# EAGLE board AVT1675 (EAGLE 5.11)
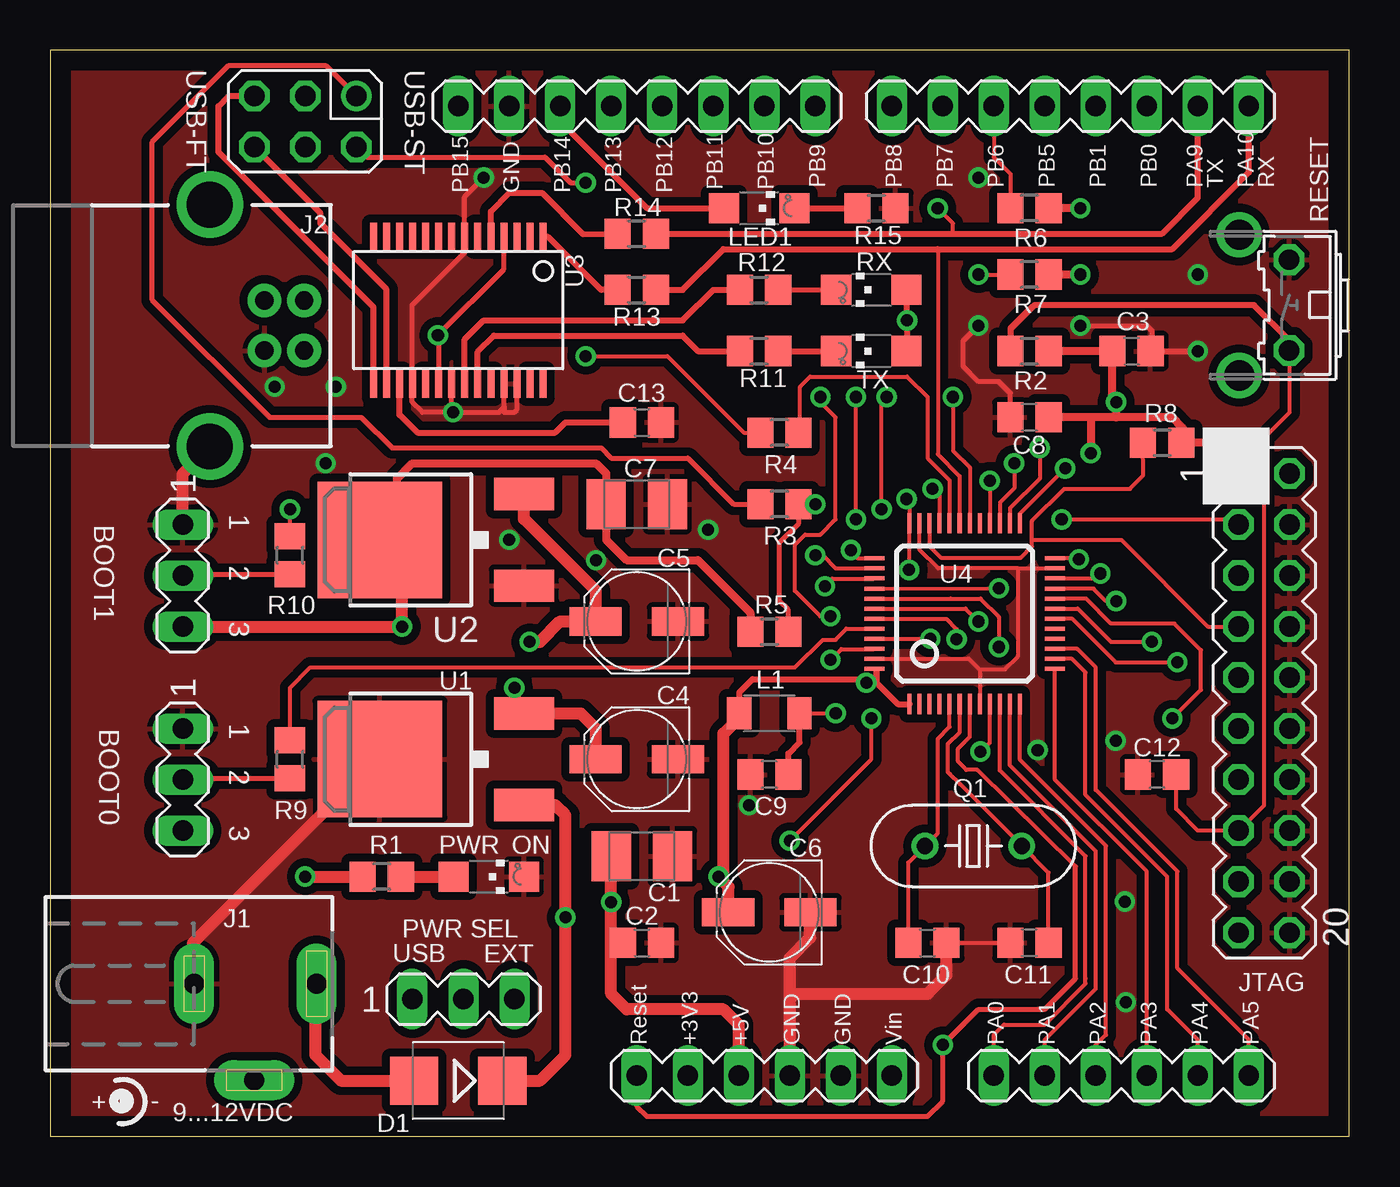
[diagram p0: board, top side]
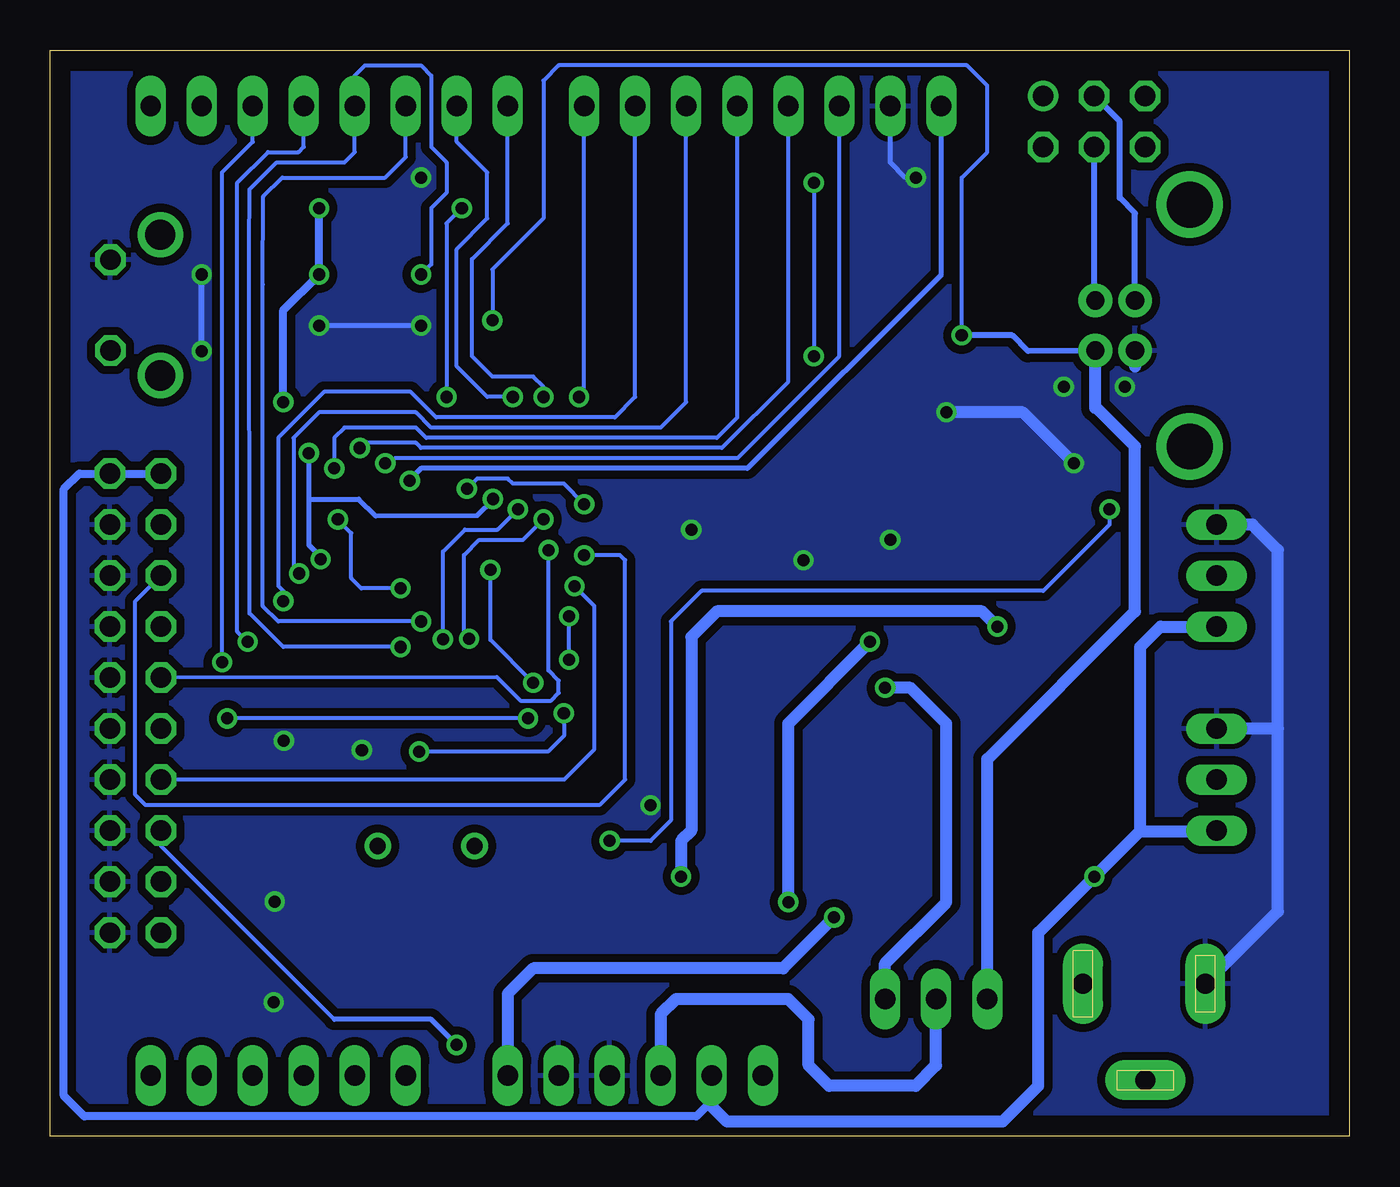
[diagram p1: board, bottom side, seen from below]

Size 64.69 x 54.07 mm. Coordinates in mm from the lower left corner, seen from the top.
Outline: 0,0 64.69,0 64.69,54.07 0,54.07 0,0
Copper layers (1*16): Top 0.035mm / dielectric 1.5mm / Bottom 0.035mm
Design rules "default *": minimum track width 8mil, minimum drill 24mil, track to track 8mil, track to pad 8mil, pad to pad 8mil, via to via 8mil, smd to smd 8mil, copper to edge 40mil, drill to drill 8mil, minimum pad ring 10mil, minimum via ring 8mil, stop-mask expansion 4mil, vias tented up to drill 0mil, thermal gap 10mil

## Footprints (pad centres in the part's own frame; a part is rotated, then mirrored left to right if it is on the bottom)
MA03-1 = drill 1.016 long: 1 -2.54,0; 2 0,0; 3 2.54,0
B/3528-21R = smd 1.95 x 2.5: + 1.525,0; - -1.525,0
C0805 = smd 1.3 x 1.5: 1 -0.95,0; 2 0.95,0
PANASONIC_C = smd 2.6 x 1.4: + 2.05,0; - -2.05,0
SMB = smd 2.4 x 2.4: A 2.2,0; C -2.2,0
DCJ0202 = drill 1 pad 2 long: 1 0,3.1; 2 4.8,0; 3 0,-3
USB-B-PTH = drill 0.914 pad 1.676 round: D+ 0,1.25; D- 1.981,1.25; GND 0,-1.25; VBUS 1.981,-1.25 | drill 2.286 round: P$1 -2.718,-6.02; P$2 -2.718,6.02
MA10-2 = drill 1.016 octagon: 1 -11.43,-1.27; 2 -11.43,1.27; 3 -8.89,-1.27; 4 -8.89,1.27; 5 -6.35,-1.27; 6 -6.35,1.27; 7 -3.81,-1.27; 8 -3.81,1.27; 9 -1.27,-1.27; 10 -1.27,1.27; 11 1.27,-1.27; 12 1.27,1.27; 13 3.81,-1.27; 14 3.81,1.27; 15 6.35,-1.27; 16 6.35,1.27; 17 8.89,-1.27; 18 8.89,1.27; 19 11.43,-1.27; 20 11.43,1.27
L3216C = smd 1.2 x 1.6: 1 -1.5,0; 2 1.5,0
CHIPLED_1206 = smd 1.5 x 1.5: A 0,-1.75; C 0,1.75
HC49U70 = drill 0.813 round: 1 -2.413,0; 2 2.413,0
R0805 = smd 1.3 x 1.5: 1 -0.95,0; 2 0.95,0
B3F-31XX = drill 1.016 octagon: 1 -2.261,-1.245; 2 2.261,-1.245 | drill 1.499 pad 2.159 round: 3 -3.505,1.245; 4 3.505,1.245
MA06-1 = drill 1.016 long: 1 -6.35,0; 2 -3.81,0; 3 -1.27,0; 4 1.27,0; 5 3.81,0; 6 6.35,0
MA08-1 = drill 1.016 long: 1 -8.89,0; 2 -6.35,0; 3 -3.81,0; 4 -1.27,0; 5 1.27,0; 6 3.81,0; 7 6.35,0; 8 8.89,0
DPACK = smd 1.6 x 3: 1 -2.28,-4.8; 3 2.28,-4.8 | smd 5.8 x 6.2: 4 0,2.38
SSOP28DB = smd 0.348 x 1.397: 1 -4.225,-3.656; 2 -3.575,-3.656; 3 -2.925,-3.656; 4 -2.275,-3.656; 5 -1.625,-3.656; 6 -0.975,-3.656; 7 -0.325,-3.656; 8 0.325,-3.656; 9 0.975,-3.656; 10 1.625,-3.656; 11 2.275,-3.656; 12 2.925,-3.656; 13 3.575,-3.656; 14 4.225,-3.656; 15 4.225,3.656; 16 3.575,3.656; 17 2.925,3.656; 18 2.275,3.656; 19 1.625,3.656; 20 0.975,3.656; 21 0.325,3.656; 22 -0.325,3.656; 23 -0.975,3.656; 24 -1.625,3.656; 25 -2.275,3.656; 26 -2.925,3.656; 27 -3.575,3.656; 28 -4.225,3.656
TQFP48 = smd 0.2 x 1: 1 -2.75,-4.5; 2 -2.25,-4.5; 3 -1.75,-4.5; 4 -1.25,-4.5; 5 -0.75,-4.5; 6 -0.25,-4.5; 7 0.25,-4.5; 8 0.75,-4.5; 9 1.25,-4.5; 10 1.75,-4.5; 11 2.25,-4.5; 12 2.75,-4.5; 25 2.75,4.5; 26 2.25,4.5; 27 1.75,4.5; 28 1.25,4.5; 29 0.75,4.5; 30 0.25,4.5; 31 -0.25,4.5; 32 -0.75,4.5; 33 -1.25,4.5; 34 -1.75,4.5; 35 -2.25,4.5; 36 -2.75,4.5 | smd 1 x 0.2: 13 4.5,-2.75; 14 4.5,-2.25; 15 4.5,-1.75; 16 4.5,-1.25; 17 4.5,-0.75; 18 4.5,-0.25; 19 4.5,0.25; 20 4.5,0.75; 21 4.5,1.25; 22 4.5,1.75; 23 4.5,2.25; 24 4.5,2.75; 37 -4.5,2.75; 38 -4.5,2.25; 39 -4.5,1.75; 40 -4.5,1.25; 41 -4.5,0.75; 42 -4.5,0.25; 43 -4.5,-0.25; 44 -4.5,-0.75; 45 -4.5,-1.25; 46 -4.5,-1.75; 47 -4.5,-2.25; 48 -4.5,-2.75
MA03-2 = drill 1.016 round: 1 -2.54,-1.27 | drill 1.016 octagon: 2 -2.54,1.27; 3 0,-1.27; 4 0,1.27; 5 2.54,-1.27; 6 2.54,1.27

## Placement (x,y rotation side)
BOOT0  [MA03-1]  6.6,17.75 270 top
BOOT1  [MA03-1]  6.6,27.91 270 top
C1  10uF  [B/3528-21R]  29.46,13.94 180 top
C2  100nF  [C0805]  29.46,9.63 0 top
C3  100nF  [C0805]  53.85,39.09 0 top
C4  [PANASONIC_C]  29.21,18.77 180 top
C5  [PANASONIC_C]  29.21,25.63 180 top
C6  [PANASONIC_C]  35.81,11.15 180 top
C7  10uF  [B/3528-21R]  29.21,31.47 180 top
C8  100nF  [C0805]  48.77,35.79 180 top
C9  100nF  [C0805]  35.81,18.01 180 top
C10  22pF  [C0805]  43.69,9.63 0 top
C11  22pF  [C0805]  48.77,9.63 180 top
C12  100nF  [C0805]  55.12,18.01 180 top
C13  100nF  [C0805]  29.46,35.53 0 top
D1  [SMB]  20.32,2.77 180 top
J1  [DCJ0202]  10.16,7.59 270 top
J2  USBPTH  [USB-B-PTH]  10.67,40.36 0 top
JTAG  [MA10-2]  60.45,21.56 270 top
L1  [L3216C]  35.81,21.06 180 top
LED1  [CHIPLED_1206]  35.31,46.2 270 top
PWR  [CHIPLED_1206]  21.84,12.93 270 top
Q1  8MHz  [HC49U70]  45.97,14.45 0 top
R1  1k  [R0805]  16.51,12.93 180 top
R2  10k  [R0805]  48.77,39.09 0 top
R3  22  [R0805]  36.32,31.47 180 top
R4  22  [R0805]  36.32,35.03 180 top
R5  1,5k  [R0805]  35.81,25.12 0 top
R6  4,7k  [R0805]  48.77,46.2 180 top
R7  4,7k  [R0805]  48.77,42.9 180 top
R8  10k  [R0805]  55.37,34.52 180 top
R9  10k  [R0805]  11.94,18.77 90 top
R10  10k  [R0805]  11.94,28.93 90 top
R11  1k  [R0805]  35.31,39.09 0 top
R12  1k  [R0805]  35.31,42.14 0 top
R13  1k  [R0805]  29.21,42.14 0 top
R14  1k  [R0805]  29.21,44.93 0 top
R15  1k  [R0805]  41.15,46.2 0 top
RESET  [B3F-31XX]  60.45,41.38 90 top
RX  [CHIPLED_1206]  40.89,42.14 90 top
SV2  [MA06-1]  53.34,3.02 0 top
SV3  [MA06-1]  35.56,3.02 0 top
SV4  [MA08-1]  50.8,51.28 0 top
SV5  [MA08-1]  29.21,51.28 0 top
TX  [CHIPLED_1206]  40.89,39.09 90 top
U1  78M05  [DPACK]  18.8,18.77 90 top
U2  LM11117 3V3  [DPACK]  18.8,29.69 90 top
U3  FT232RL  [SSOP28DB]  20.32,41.12 180 top
U4  STM32F10XCXT6  [TQFP48]  45.54,26.02 0 top
USB  VEXT  [MA03-1]  20.57,6.83 0 top
USB-FT  [MA03-2]  12.7,50.52 180 top

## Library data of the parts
BOOT0 BOOT1 JTAG SV4 SV5 USB = con-lstb_v2; OC_FARNELL: unknown; OC_NEWARK: unknown
C1-C13 L1 R1-R15 = rcl
D1 = diode
J1 = con-jack; OC_FARNELL: unknown; OC_NEWARK: unknown
J2 U3 = moja
LED1 PWR RX TX = led
Q1 = crystal; OC_FARNELL: unknown; OC_NEWARK: unknown
RESET = switch-omron; MPN: B3F-3100; OC_FARNELL: 959704; OC_NEWARK: 36M3582
SV2 SV3 USB-FT = con-lstb_v2a; OC_FARNELL: unknown; OC_NEWARK: unknown
U1 U2 = v-reg
U4 = stm32

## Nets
+3V3: BOOT0.3 BOOT1.3 C3.1 C6.+ C7.+ C8.1 JTAG.1 JTAG.2 L1.2 R1.2 R2.2 R5.1 R6.1 R7.1 R8.1 SV3.2 U2.4 U4.1 U4.24 U4.36 U4.48
+5V: C1.+ C2.1 C5.+ SV3.3 U2.3 USB.2
BOOT0: R9.2 U4.44
GND: BOOT0.1 BOOT1.1 C1.- C2.2 C3.2 C4.- C5.- C6.- C7.- C8.2 C9.2 C10.2 C11.2 C12.2 C13.2 J1.3 J2.GND JTAG.4 JTAG.6 JTAG.8 JTAG.10 JTAG.12 JTAG.14 JTAG.16 JTAG.18 JTAG.20 PWR.C R15.2 RESET.2 SV3.4 SV3.5 SV5.2 U1.4 U2.1 U3.7 U3.18 U3.21 U3.25 U3.26 U4.8 U4.23 U4.35 U4.47
N$1: J2.D+ USB-FT.3
N$2: R3.2 USB-FT.1
N$3: R4.2 USB-FT.2
N$4: D1.A J1.1
N$5: PWR.A R1.1
N$6: C13.1 U3.17
N$7: R13.1 U3.1
N$8: LED1.C R15.1
N$9: U3.15 USB-FT.5
N$10: J2.D- USB-FT.4
N$11: U3.16 USB-FT.6
N$12: R14.1 U3.5
N$13: C9.1 L1.1 U4.9
N$14: R11.1 U3.23
N$15: R12.1 U3.22
N$16: R11.2 TX.C
N$17: R12.2 RX.C
N$26: C4.+ U1.3 USB.3
N$44: BOOT1.2 R10.1
N$45: BOOT0.2 R9.1
NRST: C12.1 JTAG.15 R2.1 RESET.1 SV3.1 U4.7
PA0: SV2.1 U4.10
PA1: SV2.2 U4.11
PA2: SV2.3 U4.12
PA3: SV2.4 U4.13
PA4: SV2.5 U4.14
PA5: SV2.6 U4.15
PA6: U4.16
PA7: U4.17
PA8: U4.29
PA9: R14.2 SV4.7 U4.30
PA10: R13.2 SV4.8 U4.31
PA13: JTAG.7 R8.2 U4.34
PA14: JTAG.9 U4.37
PA15: JTAG.5 U4.38
PB0: SV4.6 U4.18
PB1: SV4.5 U4.19
PB2: R10.2 U4.20
PB3: JTAG.13 U4.39
PB4: JTAG.3 U4.40
PB5: R7.2 SV4.4 U4.41
PB6: R6.2 SV4.3 U4.42
PB7: SV4.2 U4.43
PB8: SV4.1 U4.45
PB9: SV5.8 U4.46
PB10: SV5.7 U4.21
PB11: SV5.6 U4.22
PB12: SV5.5 U4.25
PB13: SV5.4 U4.26
PB14: LED1.A SV5.3 U4.27
PB15: SV5.1 U4.28
PC13: U4.2
PC14: U4.3
PC15: U4.4
USBDM: R4.1 U4.32
USBDP: R3.1 R5.2 U4.33
VIN: D1.C SV3.6 U1.1
VUSB: J2.VBUS RX.A TX.A U3.4 U3.20 USB.1
X1: C10.1 Q1.1 U4.5
X2: C11.1 Q1.2 U4.6

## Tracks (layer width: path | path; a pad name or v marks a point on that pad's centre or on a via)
+3V3  (via drill 0.6)
  Top 0.203: v42.65,31.72 42.79,31.59 U4.36 42.79,27.96 v42.77,28.19 | U4.24 51.19,28.77 v51.23,28.73 | 41.15,22.58 v40.64,22.58
  Top 0.254: 41.15,23.16 U4.48 41.15,23.22
  Top 0.305: U4.1 42.21,21.52 41.15,22.58 41.15,23.16 | L1.2 34.31,22.1 34.98,22.76 41.15,22.76 41.15,23.22
  Top 0.406: v51.31,46.2 R6.1 | v51.31,42.9 R7.1 | JTAG.1 59.18,33.76 58.42,34.52 R8.1 56.39,34.58 56.39,35.28 55.88,35.79 53.09,35.79 | 51.82,35.79 C8.1 | 51.82,35.79 v51.82,34.01 | 53.09,35.79 51.82,35.79 | 53.09,35.79 v53.09,36.55 52.9,36.74 C3.1 R2.2 | R5.1 34.86,26.07 32.26,28.68 28.7,28.68 27.69,29.69 C7.+ 27.68,33 27.18,33.5 18.03,33.5 17.27,32.74 17.27,30.55 U2.4
  Top 0.61: C6.+ 33.76,12.4 33.78,12.42 v33.27,12.93 | L1.2 34.31,20.83 33.53,20.04 33.53,13.18 v33.27,12.93 | v12.7,12.93 R1.2 | v33.27,12.93 33.76,12.44 | 27.18,31.72 27.43,31.47 C7.+ | BOOT1.3 v17.53,25.37 17.53,27.66 16.51,29.69 U2.4
  Bottom 0.203: v42.77,28.19 42.77,24.71 v40.64,22.58
  Bottom 0.254: v42.65,31.72 42.65,31.7 43.43,30.91 48.49,30.89 49.33,31.72 51.82,31.72 | v51.23,28.73 51.23,28.85 51.82,29.44 51.82,31.72 | v51.82,34.01 51.82,31.72
  Bottom 0.305: SV3.2 31.75,1.75
  Bottom 0.406: v51.31,46.2 v51.31,42.9 53.09,41.12 v53.09,36.55 | 31.75,1.75 32.51,0.99 62.99,0.99 64.01,2.01 64.01,32.23 63.25,32.99 JTAG.2 JTAG.1 | 31.75,1.5 SV3.2
  Bottom 0.61: v33.27,12.93 33.27,14.71 32.77,15.21 32.77,24.87 31.5,26.14 18.29,26.14 v17.53,25.37 | 10.41,15.21 10.41,15.19 7.87,15.19 | 7.87,15.19 7.75,15.19 | 10.41,15.21 10.41,24.36 9.4,25.37 BOOT1.3 | 10.41,15.21 v12.7,12.93 15.49,10.13 15.49,2.51 17.27,0.74 30.99,0.74 31.75,1.5 | BOOT0.3 7.85,15.21 7.87,15.19
+5V  (via drill 0.6)
  Top 0.254: 27.94,9.63 C2.1
  Top 0.61: SV3.3 34.29,5.56 33.53,6.32 28.7,6.32 27.94,7.09 27.94,9.12 27.94,9.63 v27.94,11.66 C1.+ | C5.+ 27.15,26.54 | v23.88,24.61 24.38,24.61 25.4,25.63 C5.+ | U2.3 23.6,30.73 27.18,27.15 27.18,25.65 C5.+
  Bottom 0.61: USB.2 20.57,3.53 21.59,2.51 25.91,2.51 26.92,3.53 26.92,5.82 27.94,6.83 33.53,6.83 34.29,6.07 SV3.3 | v23.88,24.61 27.94,20.55 v27.94,11.66
BOOT0
  Top 0.203: R9.2 11.94,22.33 12.95,23.34 37.08,23.34 38.48,24.71 39.12,24.71 39.65,25.27 U4.44
GND  (via drill 0.6)
  Top 0.203: C10.2 C11.2 | 46.29,23.23 U4.8 | 46.29,23.23 45.75,23.77 U4.47 | U4.35 43.29,29.2 44.22,28.27 48.21,28.27 | 48.21,28.27 U4.23 | 48.21,28.27 48.21,23.9 47.55,23.24 46.3,23.24 46.29,23.23
  Top 0.254: U3.26 23.25,36.17 23.11,36.04 22.61,36.04 22.61,36.3 | 22.61,36.3 22.61,37.46 | 22.61,37.46 U3.25 | U3.21 20,36.11 v20.07,36.04 | v20.07,36.04 22.35,36.04 22.61,36.3 | 22.61,37.46 22.61,37.57 | v21.59,47.73 20.64,46.78 U3.7 20.64,43.99 18.03,41.38 18.03,37.48 U3.18 18.03,36.55 18.54,36.04 v20.07,36.04 | 13.72,33.4 v13.72,33.5 | C8.2 47.82,36.99 47.24,37.57 46.23,37.57 45.47,38.33 45.47,39.6 v46.23,40.36 | v51.31,40.36 54.61,40.36 54.86,40.11 54.86,39.16 C3.2
  Top 0.305: C3.2 v57.15,39.09
  Top 0.61: BOOT1.1 6.6,32.99 7.62,34.01 7.62,34.52 | U1.4 16.26,18.77 7.11,9.63 7.11,7.64 J1.3 | SV3.4 36.83,6.83 | 36.83,6.83 36.83,8.86 37.85,9.88 37.85,11.13 C6.- | C10.2 44.64,8.04 43.69,7.09 37.08,7.09 36.83,6.83
  Bottom 0.254: v21.59,47.73 22.1,47.73 22.86,48.49 SV5.2 | v46.23,40.36 v51.31,40.36
  Bottom 0.305: v57.15,39.09 v57.15,42.9
  Bottom 0.61: 3.56,20.29 3.56,29.18 4.83,30.45 BOOT1.1 | 3.56,20.29 BOOT0.1 | 3.56,20.29 3.56,11.2 J1.3 | v20.07,36.04 16.26,36.04 v13.72,33.5 | 10.67,38.33 J2.GND
  other vias: 49.17,19.23 53.06,19.69 46.23,47.73 32.77,30.2 11.18,37.31 14.22,37.31 22.86,29.69 34.8,16.48 27.18,28.68 53.52,11.68 53.57,6.68
  pour Top (isolate 0.406): -0.76,54.33 65.28,54.58 65.28,-0.03 -1.02,-0.79
  pour Bottom (isolate 0.406): -2.54,55.09 65.79,55.09 65.53,-1.04 -2.54,-1.8
N$1
  Bottom 0.305: J2.D+ 10.67,45.95 11.43,46.71 11.43,50.52 USB-FT.3
N$2
  Top 0.254: R3.2 34.04,31.47 31.75,33.76 27.94,33.76 27.43,34.26 17.02,34.26 15.49,35.79 10.92,35.79 5.08,41.63 5.08,49.5 8.89,53.31 13.72,53.31 USB-FT.1
N$3  (via drill 0.6)
  Top 0.203: R4.2 34.54,35.03 30.73,38.84 v26.67,38.84
  Top 0.254: v26.67,47.47 25.91,47.47 24.64,48.74 15.75,48.74 USB-FT.2
  Bottom 0.203: v26.67,47.47 v26.67,38.84
N$4
  Top 0.61: J1.1 13.21,7.54 13.21,4.04 14.48,2.77 D1.A
N$5
  Top 0.61: R1.1 PWR.A
N$6
  Top 0.305: U3.17 17.39,35.92 18.29,35.03 25.15,35.03 25.65,35.53 C13.1
N$7
  Top 0.305: U3.1 24.79,44.78 27.43,42.14 R13.1
N$8
  Top 0.305: LED1.C R15.1
N$9
  Top 0.305: U3.15 16.09,41.28 8.38,49 8.38,51.28 8.89,51.79 USB-FT.5
N$10
  Bottom 0.305: J2.D- 12.7,41.61 USB-FT.4
N$11
  Top 0.305: U3.16 16.75,42.16 13.46,45.44 13.46,45.95 USB-FT.6
N$12
  Top 0.305: R14.1 26.53,44.92 24.49,46.96 22.86,46.96 21.94,46.05 U3.5
N$13  (via drill 0.6)
  Top 0.203: U4.9 46.79,19.59 v46.33,19.15 | L1.1 v39.12,21.06
  Top 0.305: L1.1 37.31,19.61 36.75,19.05 C9.1
  Bottom 0.203: v46.33,19.15 41,19.15 39.9,19.15 39.12,19.94 v39.12,21.06
N$14
  Top 0.305: U3.23 21.29,39.05 22.1,39.85 31.5,39.85 32.26,39.09 R11.1
N$15
  Top 0.305: R12.1 33.02,42.14 31.5,40.61 21.59,40.61 20.64,39.67 U3.22
N$16
  Top 0.305: R11.2 TX.C
N$17
  Top 0.254: R12.2 RX.C
N$26  (via drill 0.6)
  Top 0.61: v23.11,22.33 23.11,21.53 U1.3 26.42,21.06 27.16,20.31 C4.+
  Bottom 0.61: USB.3 23.11,8.61 20.07,11.66 20.07,20.55 21.84,22.33 v23.11,22.33
N$44
  Top 0.203: BOOT1.2 7.69,27.98
  Top 0.254: 7.69,27.98 R10.1
N$45
  Top 0.203: BOOT0.2 7.69,17.82
  Top 0.254: 7.69,17.82 R9.1
NRST  (via drill 0.6)
  Top 0.203: U4.7 45.8,19.89 45.21,19.3 45.21,18.67 45.62,18.24 46.17,18.24 51.05,13.44 | C12.1 56.07,16.3 57.15,15.21 JTAG.15 60.45,16.48 60.45,34.77 61.72,36.04 61.72,39.09
  Top 0.254: 51.05,13.44 51.05,7.85 49.53,6.32 46.23,6.32 v44.45,4.55 44.45,1.75 43.69,0.99 29.72,0.99 29.21,1.5 SV3.1
  Top 0.305: 61.7,39.62 RESET.1 | 61.7,39.62 59.94,41.38 49.02,41.38 | 49.02,41.38 48.72,41.12 47.83,40.23 R2.1 47.82,40.17 49.02,41.38 | 61.7,39.62 61.72,39.6 61.72,39.09
  Bottom 0.203: JTAG.15 59.18,14.45 50.55,5.82
  Bottom 0.254: 50.55,5.82 45.72,5.82 v44.45,4.55
PA0
  Top 0.203: U4.10 47.29,18.22 51.56,13.94 51.56,7.85 51.56,7.59 49.53,5.56 47.5,5.56 46.99,5.05 SV2.1
PA1
  Top 0.203: U4.11 47.79,18.48 52.07,14.2 52.07,7.34 49.53,4.8 SV2.2
PA2
  Top 0.203: U4.12 48.29,18.74 52.58,14.45 52.58,5.05 52.07,4.55 SV2.3
PA3
  Top 0.203: U4.13 50.04,17.75 54.61,13.18 SV2.4
PA4
  Top 0.203: U4.14 50.88,23.77 51.56,23.09 51.56,16.99 55.63,12.93 55.63,6.32 57.15,4.8 SV2.5
PA5
  Top 0.203: U4.15 51.14,24.27 52.07,23.34 52.07,17.25 56.13,13.18 56.13,8.36 59.69,4.8 SV2.6
PA9  (via drill 0.6)
  Top 0.203: 44.96,44.93 44.96,45.44 v44.2,46.2 | v44.96,36.8 44.96,34.14 45.8,33.3 U4.30
  Top 0.305: R14.2 44.96,44.93 55.37,44.93 57.15,46.71 SV4.7
  Bottom 0.203: v44.2,46.2 44.96,45.44 v44.96,36.8
PA10
  Top 0.203: 44.2,44.17 44.2,33.96 45.29,32.87 U4.31
  Top 0.305: SV4.8 59.69,47.98 55.88,44.17 44.2,44.17 33.53,44.17 31.5,42.14 R13.2
PA13
  Top 0.203: JTAG.7 57.66,25.37 53.34,29.69 48.89,29.69 | 48.89,29.69 48.89,29.36 48.34,28.8 44.35,28.8 43.79,29.36 U4.34 | 48.89,29.69 48.89,30.63 50.49,32.23 53.77,32.23 54.43,32.92 R8.2
PA14  (via drill 0.6)
  Top 0.203: v39.88,29.18 39.88,29.08 40.21,28.78 41.02,28.78 U4.37
  Bottom 0.203: JTAG.9 42.44,22.86 41.27,21.69 39.75,21.69 39.37,22.07 39.37,22.68 39.88,23.19 v39.88,29.18
PA15  (via drill 0.6)
  Top 0.203: v38.1,28.93 38.48,28.93 39.12,28.27 41.01,28.27 U4.38
  Bottom 0.203: JTAG.5 60.45,26.64 60.45,16.99 59.94,16.48 37.34,16.48 36.07,17.75 36.07,28.68 36.32,28.93 v38.1,28.93
PB0  (via drill 0.6)
  Top 0.203: v56.13,23.6 53.06,23.6 50.88,25.78 50.05,25.78 U4.18
  Bottom 0.203: SV4.6 54.61,49.5 56.13,47.98 v56.13,23.6
PB1  (via drill 0.6)
  Top 0.203: U4.19 51.18,26.27 52.83,24.61 v54.86,24.61
  Bottom 0.203: v54.86,24.61 55.37,25.12 55.37,47.47 53.85,49 52.32,49 52.07,49.25 SV4.5
PB2  (via drill 0.6)
  Top 0.203: U4.20 51.59,26.77 52.83,25.53 55.98,25.53 57.3,24.21 57.3,22.22 v55.88,20.8 | v40.89,20.8 40.89,18.77 v36.83,14.71 | R10.2 v11.94,31.22
  Bottom 0.203: v40.89,20.8 v55.88,20.8 | v36.83,14.71 34.8,14.71 33.78,15.72 33.78,25.63 32.26,27.15 15.24,27.15 11.94,30.45 v11.94,31.22
PB3  (via drill 0.6)
  Top 0.203: v38.58,27.38 38.94,27.76 41.01,27.76 U4.39
  Bottom 0.203: JTAG.13 39.12,17.75 37.59,19.28 37.59,26.39 v38.58,27.38
PB4  (via drill 0.6)
  Top 0.203: U4.40 v47.24,27.28 | v50.37,30.71 58.42,30.71 58.67,30.45 JTAG.3
  Bottom 0.203: v47.24,27.28 49.2,27.28 49.71,27.79 49.71,30.02 v50.37,30.71
PB5  (via drill 0.6)
  Top 0.203: U4.41 44.83,26.77 46.33,26.77 47.24,25.86 v47.24,24.36 | v46.23,42.9 R7.2
  Bottom 0.203: 46.99,24.36 v47.24,24.36 53.09,24.36 54.76,26.03 54.79,44.2 54.76,47.14 53.42,48.49 50.04,48.49 49.53,49 SV4.4 49.53,52.81 49.02,53.31 46.23,53.31 45.72,52.81 45.72,49.25 44.96,48.49 44.96,46.96 45.72,46.2 45.72,43.41 v46.23,42.9
PB6  (via drill 0.6)
  Top 0.203: U4.42 45.59,26.27 v46.23,25.63 | R6.2 47.82,47.91 46.99,48.74 SV4.3
  Bottom 0.203: SV4.3 46.99,48.74 48.01,47.73 53.14,47.73 54.08,46.79 54.1,42.39 54.1,26.39 53.34,25.63 v46.23,25.63
PB7  (via drill 0.6)
  Top 0.203: v41.4,31.22 41.4,36.55 v41.66,36.8 | v45.14,24.74 45.14,25.25 44.63,25.76 44.37,25.76 41.05,25.76 U4.43
  Bottom 0.203: SV4.2 44.45,49.5 42.93,47.98 42.93,45.69 44.45,44.17 44.45,38.33 42.93,36.8 v41.66,36.8 | v41.4,31.22 42.42,30.2 44.04,30.2 45.14,29.11 v45.14,24.74
PB8  (via drill 0.6)
  Top 0.203: U4.45 43.33,24.77 v43.84,24.76 | v40.13,30.71 v40.13,36.8
  Bottom 0.203: v43.84,24.76 44.09,25.02 44.09,28.93 43.33,29.69 41.15,29.69 v40.13,30.71 | v40.13,36.8 40.13,37.31 40.64,37.82 42.67,37.82 43.69,38.84 43.69,43.66 41.91,45.44 SV4.1
PB9  (via drill 0.6)
  Top 0.203: v38.35,36.8 38.35,36.55 39.12,35.79 39.12,30.71 38.35,29.95 37.59,29.95 37.08,29.44 37.08,27.15 38.35,25.88 v38.86,25.88 | v38.86,23.72 39.39,24.26 41,24.26 U4.46
  Bottom 0.203: v38.35,36.8 38.1,37.06 SV5.8 | v38.86,23.72 v38.86,25.88
PB10  (via drill 0.6)
  Top 0.203: U4.21 51.95,27.27 52.58,26.64 v53.09,26.64
  Bottom 0.203: SV5.7 35.56,36.8 36.58,35.79 45.47,35.79 46.74,37.06 51.05,37.06 53.34,34.77 53.34,27.41 53.09,27.15 v53.09,26.64
PB11  (via drill 0.6)
  Top 0.203: v52.3,28.02 51.99,27.76 U4.22
  Bottom 0.203: SV5.6 33.02,36.55 34.29,35.28 45.72,35.28 46.48,36.04 51.31,36.04 52.58,34.77 52.58,28.3 v52.3,28.02
PB12  (via drill 0.6)
  Top 0.203: U4.25 48.3,31 v50.55,33.25
  Bottom 0.203: v50.55,33.25 50.55,34.77 50.04,35.28 46.48,35.28 45.97,34.77 31.5,34.77 30.48,35.79 SV5.5
PB13  (via drill 0.6)
  Top 0.203: v49.28,34.26 49.28,32.74 47.8,31.27 47.8,30.53 U4.26
  Bottom 0.203: SV5.4 27.94,37.57 31.24,34.26 46.23,34.26 46.48,34.52 49.02,34.52 v49.28,34.26
PB14  (via drill 0.6)
  Top 0.203: v48.01,33.5 48.01,32.26 47.3,31.55 U4.27
  Top 0.305: LED1.A 29.72,46.2 25.4,50.52 SV5.3
  Bottom 0.203: SV5.3 25.4,38.84 30.48,33.76 47.5,33.76 v48.01,33.5
PB15  (via drill 0.6)
  Top 0.203: v46.79,32.64 U4.28
  Bottom 0.203: 46.79,32.69 v46.79,32.64
  Bottom 0.254: SV5.1 20.32,42.9 29.97,33.25 46.23,33.25 46.79,32.69
USBDM
  Top 0.203: U4.32 44.79,32.65 43.69,33.76 43.69,36.8 42.67,37.82 37.85,37.82 37.34,37.31 37.34,35.09 R4.1
USBDP  (via drill 0.6)
  Top 0.203: U4.33 44.29,31.88 v43.94,32.23 | 37.29,31.46 38.08,31.46 v38.1,31.47
  Top 0.254: R5.2 36.76,26.2 36.32,26.64 36.32,29.57 37.29,30.53 37.29,31.46 R3.1
  Bottom 0.203: v38.1,31.47 39.12,32.49 41.66,32.49 41.91,32.74 43.43,32.74 v43.94,32.23
VIN  (via drill 0.6)
  Top 0.61: U1.1 25.14,16.49 25.65,15.98 v25.65,10.9 25.65,4.04 24.38,2.77 D1.C
  Bottom 0.61: SV3.6 41.91,7.09 40.64,8.36 28.19,8.36 v25.65,10.9
VUSB  (via drill 0.6)
  Top 0.203: v19.3,39.87 19.34,39.83
  Top 0.254: 19.34,39.83 U3.20 | U3.4 22.59,43.16 v19.3,39.87
  Top 0.305: RX.A 42.67,42.11 v42.67,40.61 42.67,39.29 TX.A
  Bottom 0.203: v19.3,39.87 19.3,47.73 18.03,49 18.03,52.3 19.05,53.31 39.37,53.31 40.13,52.55 40.13,45.69 42.67,43.15 v42.67,40.61
  Bottom 0.305: J2.VBUS 16,39.09 16.78,39.87 v19.3,39.87
  Bottom 0.61: USB.1 18.03,18.77 10.67,26.14 10.67,34.34 12.59,36.27 12.65,36.27 J2.VBUS
X1
  Top 0.203: U4.5 44.79,20.38 44.2,19.79 44.2,15.72 44.21,15.1 Q1.1 42.74,13.63 C10.1
X2
  Top 0.203: C11.1 49.72,13.12 Q1.2 45.29,17.55 44.81,18.03 44.7,18.14 44.7,19.53 45.29,20.12 U4.6

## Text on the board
tNames: USB-ST | PB15 | GND | PB14 | PB13 | PB12 | PB11 | PB10 | PB9 | PB8 | PB7 | PB6 | PB5 | PB1 | PB0 | PA9 | TX | PA10 | RX | 1 | 2 | 3 | 1 | 2 | 3 | ON | PWR SEL | EXT | Reset | +3V3 | +5V | GND | GND | Vin | PA0 | PA1 | PA2 | PA3 | PA4 | PA5 | + | - | 9...12VDC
